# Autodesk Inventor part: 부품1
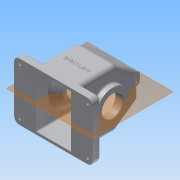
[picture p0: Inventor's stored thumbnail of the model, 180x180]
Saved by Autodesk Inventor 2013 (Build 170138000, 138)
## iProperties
Created: 2016-12
Part Number: 부품1
Material: 알루미늄 6061
Document SubType Name: Modeling
Designer: Administrator
Density: 2.71 g/cm^3
Mass: 1063.77 g
Surface Area: 1146.35 cm^2
Volume: 392.536 cm^3
Author: Administrator
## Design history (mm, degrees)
sketch "스케치2"
  geometry: L1 (-75, -55)-(75, -55); L2 (75, -55)-(75, 55); L3 (75, 55)-(-75, 55); L4 (-75, 55)-(-75, -55); L5 (-75, -55)-(75, 55); L6 (75, -55)-(-75, 55); 1 further point
  constraints: 12 end point, 2 midpoint, 2 parallel, 1 horizontal, 1 perpendicular
  dimensions: "d0" = 150 distance of L2.end L3.end; "d2" = 110 distance of L1.end L2.end
extrude "돌출1" new body sketch "스케치2" distance "d3" = 15; taper "d4" = 0 deg
fillet "모깎기1" dims "d5" = 10
hole "구멍1" diameter "d8" = 5; stored, may be unused: countersink angle "d12" = 90 deg, drill point angle "d14" = 118 deg; dims "d6" = 10, "d7" = 10, "d9" = 6, "d10" = 12, "d11" = 5, "d13" = 8
node "작업 평면1"
sketch "스케치4"
  geometry: L1 (100, 0)-(-10, 0) reference; L2 (-10, 0)-(-10, 15) reference; L3 (-10, 15)-(100, 15) reference; L4 (100, 15)-(100, 0) reference; L5 (-10, 15)-(-10, 80); L6 (-10, 80)-(21.509, 125); L7 (21.509, 125)-(68.491, 125); L8 (68.491, 125)-(100, 80); L9 (100, 80)-(100, 15); L10 (-10, 15)-(100, 15); 3 further points
  constraints: 12 end point, 2 midpoint, 1 collinear, 1 parallel, 1 perpendicular, 1 point on line, 1 vertical, 1 vertical alignment
  dimensions: "d22" = 35 deg angle of L6 L5; "d23" = 35 deg angle of L9 L8; "d24" = 80 distance of L1.start L8.end; "d25" = 125 distance between parallel lines of L1 L7
extrude "돌출2" join sketch "스케치4" stored distance "d26" = 77; taper "d27" = 0 deg
node "작업 평면2"
sketch "스케치5"
  geometry: L1 (-10, 80)-(21.509, 125) reference; L2 (21.509, 125)-(68.491, 125) reference; L3 (68.491, 125)-(100, 80) reference; L4 (100, 80)-(100, 0) reference; L5 (100, 0)-(-10, 0) reference; L6 (-10, 0)-(-10, 80) reference; L7 (65.888, 120)-(24.112, 120); L8 (24.112, 120)-(-5, 78.424); L9 (-5, 78.424)-(-5, 0); L10 (95, 0)-(95, 78.424); L11 (95, 78.424)-(65.888, 120); L12 (-5, 0)-(95, 0); 1 further point
  constraints: 12 end point, 2 point on line, 1 collinear, 1 other
  dimensions: "d28" = 5 distance between parallel lines of L2 L7; "d29" = 78.42351 distance of L8.end L9.end; "d30" = 50.75553 distance of L7.end L8.end; "d31" = 41.77565 distance of L7.start L7.end; "d32" = 29.11217 horizontal distance of L10.end L7.start; "d33" = 78.42351 distance of L10.start L10.end; "d34" = 100 distance of L10.start L9.end
extrude "돌출3" cut sketch "스케치5" stored distance "d35" = 67; taper "d36" = 0 deg
sketch "스케치6"
  geometry: L1 (-30.313, 65)-(120.313, 65); L2 (0, 0)-(90, 0) reference; C1 r 37.5 at (45, 65); 3 further points
  constraints: 2 end point, 2 midpoint, 1 centre point, 1 coincident, 1 horizontal, 1 vertical alignment
  dimensions: "d38" = 65 distance from line of L1.end L2; "d39" = 150.62512 distance of L1.start L1.end; "d40" = 75 diameter of C1
extrude "돌출4" join sketch "스케치6" distance "d41" = 5; taper "d42" = 0 deg
sketch "스케치7"
  geometry: L1 (-90, 0)-(0, 0) reference; C1 r 31 at (-45, 65); 2 further points
  constraints: 1 centre point, 1 midpoint, 1 vertical alignment
  dimensions: "d43" = 65 distance from line of C1.centre L1; "d44" = 62 diameter of C1
extrude "돌출5" join sketch "스케치7" distance "d45" = 10; taper "d46" = 0 deg
sketch "스케치8"
  geometry: L1 (-43.5, 102.5)-(-43.5, 27.5) reference; L2 (-19.5, 92)-(-19.5, 65); L3 (-19.5, 92)-(-33.5, 106); L4 (-33.5, 78.424)-(-33.5, 0) reference; L5 (-33.5, 65)-(-33.5, 106); L6 (-43.5, 65)-(48.5, 65); L7 (-33.5, 65)-(-19.5, 65); 1 further point
  constraints: 10 end point, 1 midpoint, 1 perpendicular, 1 point on line
  dimensions: "d49" = 24 distance between parallel lines of L2 L1; "d50" = 45 deg angle of L2 L3; "d53" = 41 distance of L5.start L3.end; "d54" = 14 horizontal distance of L2.start L3.end; "d55" = 92 distance of L6.start L6.end; "d56" = 54 diameter of L2.start L6; "d57" = 27 distance of L2.start L2.end
revolve "회전1" sketch "스케치8" stored, may be unused: angle "d58" = 90 deg
sketch "스케치9"
  geometry: C1 r 31 at (0, 0) reference; C2 r 20 at (0, 0); 1 further point
  constraints: 1 centre point, 1 coincident
  dimensions: "d59" = 40 diameter of C2
extrude "돌출6" cut sketch "스케치9" stored distance "d61" = 10; taper "d62" = 0 deg
sketch "스케치10"
  geometry: C1 r 20 at (0, 0) reference; 2 further points
  constraints: 1 vertical alignment
  dimensions: "d63" = 29 distance of C1.centre point (0, 29)
hole "구멍2" sketch "스케치10" at (0, 29) diameter "d64" = 2.459; stored, may be unused: countersink angle "d68" = 90 deg, drill point angle "d70" = 118 deg; dims "d65" = 6, "d66" = 12, "d67" = 5, "d69" = 8
sketch "스케치11"
  geometry: C1 r 20 at (0, 0) reference; 2 further points
  constraints: 1 vertical alignment
  dimensions: "d74" = 26 distance of point (0, 26) C1.centre
hole "구멍3" sketch "스케치11" at (0, 26) diameter "d75" = 2.459; stored, may be unused: countersink angle "d79" = 90 deg, drill point angle "d81" = 118 deg; dims "d76" = 6, "d77" = 12, "d78" = 5, "d80" = 8
node "작업 평면4"
sketch "스케치13"
  geometry: L1 (125, 23.491)-(125, -23.491) reference; L2 (125, 12.5)-(140, 12.5); L3 (140, 12.5)-(140, -12.5); L4 (140, -12.5)-(125, -12.5); L5 (125, -7.5)-(135, -7.5); L6 (135, -7.5)-(135, 7.5); L7 (135, 7.5)-(125, 7.5); L8 (125, 12.5)-(125, 7.5); L9 (125, -7.5)-(125, -12.5); 2 further points
  constraints: 16 end point, 4 perpendicular, 2 point on line, 1 horizontal alignment, 1 midpoint, 2 other
  dimensions: "d93" = 140 distance from line of point (0, 0) L3; "d94" = 25 distance of L2.end L3.end; "d95" = 5 distance between parallel lines of L4 L5; "d96" = 10 distance of L6.end L7.end; "d97" = 10 distance of L5.start L5.end
extrude "돌출7" join sketch "스케치13" distance "d98" = 8; taper "d99" = 0 deg
fillet "모깎기3" dims "d100" = 8
fillet "모깎기5" dims "d102" = 1
fillet "모깎기8" dims "d105" = 3
fillet "모깎기9" dims "d106" = 8
fillet "모깎기10" dims "d107" = 10
fillet "모깎기11" dims "d108" = 3
sketch "스케치14"
  geometry: L1 (26.5, 76.847)-(26.5, 18) reference; L2 (0, 0)-(130, 0) reference; 2 further points
  constraints: 1 other
  dimensions: "d109" = 38.5 horizontal distance of point (65, 45) L1.end; "d110" = 45 distance from line of point (65, 45) L2
feature "엠보싱1" sketch "스케치14" dims "d111" = 0.5, "d112" = 0
fillet "모깎기12" dims "d113" = 3, "d114" = 3
fillet "모깎기13" dims "d115" = 1
fillet "모깎기14" dims "d116" = 1
fillet "모깎기15" dims "d117" = 3
chamfer "모따기1" distance "d118" = 1; stored, may be unused: second distance "d119" = 2, angle "d120" = 45 deg
fillet "모깎기16" dims "d121" = 3
fillet "모깎기17" dims "d122" = 3
node "솔리드1"
mirror "대칭1"
mirror "대칭2"
pattern_circular "원형 패턴1" dims angle "d72" = 360 deg
pattern_circular "원형 패턴2" dims angle "d83" = 360 deg
mirror "대칭3"
node "절단 모서리 투영1"
node "절단 모서리 투영2"
other parameters: "d16" = -75, "d92" = 18
